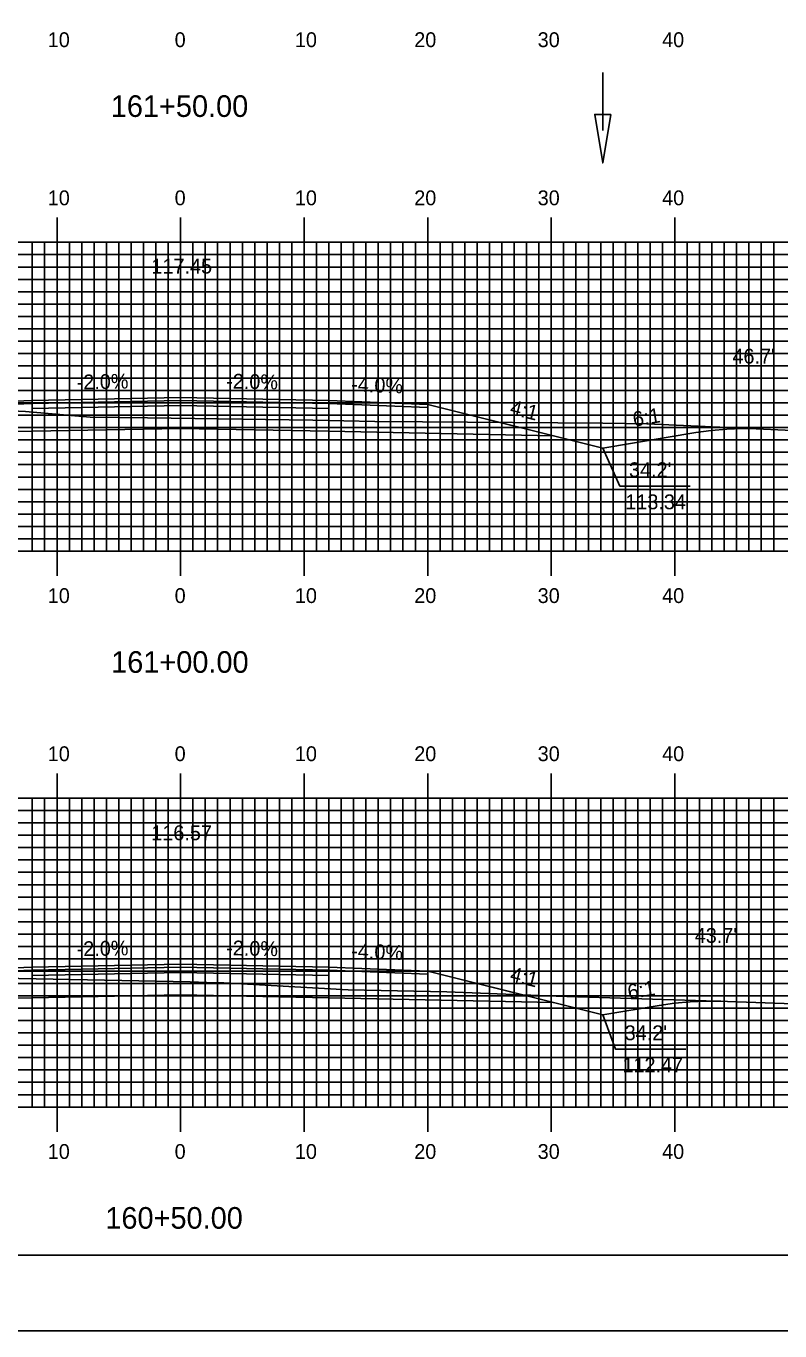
# Model space of a CAD drawing. Extents: x 1780286 to 1780629, y 442591 to 442811.
# Drawn here: x 1780439.4 to 1780500.4, y 442590.5 to 442696.2 of the extents above; entities that cross this region are included whole.
import ezdxf

# ---------------------------------------------------------------- set-up
doc = ezdxf.new("R2010")
doc.units = 0
for name, color, linetype in [('ANNOTATION', 7, 'Continuous'), ('BORDER', 7, 'Continuous'), ('D_Drainage_Ditch_Line', 7, 'Continuous'), ('D_Roadway_Centerline', 7, 'Continuous'), ('D_Roadway_Centerline_Text', 7, 'Continuous'), ('D_Roadway_Edge_Shoulder', 7, 'Continuous'), ('D_Roadway_Edge_TW', 7, 'Continuous'), ('D_Roadway_Pavement', 7, 'Continuous'), ('D_Roadway_SlopeLines', 7, 'Continuous'), ('D_Roadway_SubGrade', 7, 'Continuous'), ('D_Text_Standard', 7, 'Continuous'), ('H_V ANNOTATION', 7, 'Continuous'), ('MAJOR', 7, 'Continuous'), ('MINOR', 7, 'Continuous'), ('PLOT BOUNDARY', 7, 'Continuous'), ('S_Roadway_Centerline', 7, 'Continuous')]:
    doc.layers.add(name, color=color, linetype=linetype)

msp = doc.modelspace()

# ---------------------------------------------------------------- linework, layer by layer
at = {"layer": 'ANNOTATION'}
for points in [[(1780493.11, 442658.93), (1780487.42, 442658.93), (1780486.04, 442662.01)], [(1780492.76, 442613.35), (1780487.07, 442613.35), (1780486.04, 442616.13)]]:
    msp.add_lwpolyline(points, dxfattribs=at)
at = {"layer": 'BORDER'}
msp.add_lwpolyline([(1780302.27, 442596.67), (1780622.27, 442596.67), (1780622.27, 442806.67), (1780302.27, 442806.67)], close=True, dxfattribs=at)
at = {"layer": 'D_Drainage_Ditch_Line'}
msp.add_line((1780486.04, 442687.71), (1780486.04, 442692.41), dxfattribs=at)
msp.add_lwpolyline([(1780486.7, 442689.02), (1780485.39, 442689.02), (1780486.04, 442685.09)], close=True, dxfattribs=at)
at = {"layer": 'D_Roadway_Centerline'}
for points in [[(1780390.14, 442666.22), (1780391.39, 442666.18), (1780392.64, 442666.09), (1780393.89, 442665.95), (1780395.14, 442665.77), (1780417.69, 442662.01), (1780421.69, 442663.01), (1780431.87, 442665.55), (1780439.87, 442665.87), (1780451.87, 442666.11), (1780463.87, 442665.87), (1780471.87, 442665.55), (1780482.04, 442663.01), (1780486.04, 442662.01), (1780493.57, 442663.26), (1780494.82, 442663.44), (1780496.07, 442663.55), (1780497.32, 442663.59), (1780498.57, 442663.57)], [(1780395.38, 442619.56), (1780396.63, 442619.48), (1780397.88, 442619.36), (1780399.13, 442619.21), (1780400.38, 442619.02), (1780417.69, 442616.13), (1780421.69, 442617.13), (1780431.87, 442619.68), (1780439.87, 442620), (1780451.87, 442620.24), (1780463.87, 442620), (1780471.87, 442619.68), (1780482.04, 442617.13), (1780486.04, 442616.13), (1780490.6, 442616.89), (1780491.85, 442617.07), (1780493.1, 442617.19), (1780494.35, 442617.24), (1780495.6, 442617.23)]]:
    msp.add_lwpolyline(points, dxfattribs=at)
at = {"layer": 'D_Roadway_Edge_Shoulder'}
for points in [[(1780439.87, 442665.87), (1780431.87, 442665.55), (1780431.87, 442665.3), (1780439.87, 442665.62)], [(1780463.87, 442665.87), (1780471.87, 442665.55), (1780471.87, 442665.3), (1780463.87, 442665.62)], [(1780439.87, 442620), (1780431.87, 442619.68), (1780431.87, 442619.43), (1780439.87, 442619.75)], [(1780463.87, 442620), (1780471.87, 442619.68), (1780471.87, 442619.43), (1780463.87, 442619.75)]]:
    msp.add_lwpolyline(points, close=True, dxfattribs=at)
at = {"layer": 'D_Roadway_Edge_TW'}
for points in [[(1780439.87, 442665.62), (1780439.87, 442665.87), (1780451.87, 442666.11), (1780463.87, 442665.87), (1780463.87, 442665.62), (1780451.87, 442665.86)], [(1780439.87, 442619.75), (1780439.87, 442620), (1780451.87, 442620.24), (1780463.87, 442620), (1780463.87, 442619.75), (1780451.87, 442619.99)]]:
    msp.add_lwpolyline(points, close=True, dxfattribs=at)
at = {"layer": 'D_Roadway_Pavement'}
for points in [[(1780439.87, 442665.21), (1780439.87, 442665.62), (1780451.87, 442665.86), (1780463.87, 442665.62), (1780463.87, 442665.21), (1780451.87, 442665.45)], [(1780439.87, 442619.33), (1780439.87, 442619.75), (1780451.87, 442619.99), (1780463.87, 442619.75), (1780463.87, 442619.33), (1780451.87, 442619.57)]]:
    msp.add_lwpolyline(points, close=True, dxfattribs=at)
at = {"layer": 'D_Roadway_SlopeLines'}
for points in [[(1780471.87, 442665.55), (1780486.04, 442662.01)], [(1780486.04, 442662.01), (1780493.57, 442663.26), (1780494.82, 442663.44), (1780496.07, 442663.55), (1780497.32, 442663.59), (1780498.57, 442663.57)], [(1780471.87, 442619.68), (1780486.04, 442616.13)], [(1780486.04, 442616.13), (1780490.6, 442616.89), (1780491.85, 442617.07), (1780493.1, 442617.19), (1780494.35, 442617.24), (1780495.6, 442617.23)]]:
    msp.add_lwpolyline(points, dxfattribs=at)
at = {"layer": 'D_Roadway_SubGrade'}
for points in [[(1780439.87, 442663.37), (1780421.69, 442663.01), (1780431.87, 442665.55), (1780431.87, 442665.3), (1780439.87, 442665.62), (1780451.87, 442665.86), (1780463.87, 442665.62), (1780471.87, 442665.3), (1780471.87, 442665.55), (1780482.04, 442663.01), (1780463.87, 442663.37), (1780451.87, 442663.61)], [(1780439.87, 442617.5), (1780421.69, 442617.13), (1780431.87, 442619.68), (1780431.87, 442619.43), (1780439.87, 442619.75), (1780451.87, 442619.99), (1780463.87, 442619.75), (1780471.87, 442619.43), (1780471.87, 442619.68), (1780482.04, 442617.13), (1780463.87, 442617.5), (1780451.87, 442617.74)]]:
    msp.add_lwpolyline(points, close=True, dxfattribs=at)
at = {"layer": 'MAJOR'}
for p, q in [((1780441.87, 442680.67), (1780441.87, 442678.67)), ((1780451.87, 442680.67), (1780451.87, 442678.67)), ((1780461.87, 442680.67), (1780461.87, 442678.67)), ((1780471.87, 442680.67), (1780471.87, 442678.67)), ((1780481.87, 442680.67), (1780481.87, 442678.67)), ((1780491.87, 442680.67), (1780491.87, 442678.67)), ((1780311.87, 442678.67), (1780591.87, 442678.67)), ((1780311.87, 442678.67), (1780591.87, 442678.67)), ((1780441.87, 442653.67), (1780441.87, 442678.67)), ((1780451.87, 442653.67), (1780451.87, 442678.67)), ((1780461.87, 442653.67), (1780461.87, 442678.67)), ((1780471.87, 442653.67), (1780471.87, 442678.67)), ((1780481.87, 442653.67), (1780481.87, 442678.67)), ((1780491.87, 442653.67), (1780491.87, 442678.67)), ((1780311.87, 442673.67), (1780591.87, 442673.67)), ((1780311.87, 442668.67), (1780591.87, 442668.67)), ((1780311.87, 442663.67), (1780591.87, 442663.67)), ((1780311.87, 442658.67), (1780591.87, 442658.67)), ((1780311.87, 442653.67), (1780591.87, 442653.67)), ((1780311.87, 442653.67), (1780591.87, 442653.67)), ((1780441.87, 442651.66), (1780441.87, 442653.67)), ((1780451.87, 442651.66), (1780451.87, 442653.67)), ((1780461.87, 442651.66), (1780461.87, 442653.67)), ((1780471.87, 442651.66), (1780471.87, 442653.67)), ((1780481.87, 442651.66), (1780481.87, 442653.67)), ((1780491.87, 442651.66), (1780491.87, 442653.67)), ((1780441.87, 442635.67), (1780441.87, 442633.67)), ((1780451.87, 442635.67), (1780451.87, 442633.67)), ((1780461.87, 442635.67), (1780461.87, 442633.67)), ((1780471.87, 442635.67), (1780471.87, 442633.67)), ((1780481.87, 442635.67), (1780481.87, 442633.67)), ((1780491.87, 442635.67), (1780491.87, 442633.67)), ((1780311.87, 442633.67), (1780591.87, 442633.67)), ((1780311.87, 442633.67), (1780591.87, 442633.67)), ((1780441.87, 442608.67), (1780441.87, 442633.67)), ((1780451.87, 442608.67), (1780451.87, 442633.67)), ((1780461.87, 442608.67), (1780461.87, 442633.67)), ((1780471.87, 442608.67), (1780471.87, 442633.67)), ((1780481.87, 442608.67), (1780481.87, 442633.67)), ((1780491.87, 442608.67), (1780491.87, 442633.67)), ((1780311.87, 442628.67), (1780591.87, 442628.67)), ((1780311.87, 442623.67), (1780591.87, 442623.67)), ((1780311.87, 442618.67), (1780591.87, 442618.67)), ((1780311.87, 442613.67), (1780591.87, 442613.67)), ((1780311.87, 442608.67), (1780591.87, 442608.67)), ((1780311.87, 442608.67), (1780591.87, 442608.67)), ((1780441.87, 442606.66), (1780441.87, 442608.67)), ((1780451.87, 442606.66), (1780451.87, 442608.67)), ((1780461.87, 442606.66), (1780461.87, 442608.67)), ((1780471.87, 442606.66), (1780471.87, 442608.67)), ((1780481.87, 442606.66), (1780481.87, 442608.67)), ((1780491.87, 442606.66), (1780491.87, 442608.67))]:
    msp.add_line(p, q, dxfattribs=at)
at = {"layer": 'MINOR'}
for p, q in [((1780439.87, 442653.67), (1780439.87, 442678.67)), ((1780440.87, 442653.67), (1780440.87, 442678.67)), ((1780442.87, 442653.67), (1780442.87, 442678.67)), ((1780443.87, 442653.67), (1780443.87, 442678.67)), ((1780444.87, 442653.67), (1780444.87, 442678.67)), ((1780445.87, 442653.67), (1780445.87, 442678.67)), ((1780446.87, 442653.67), (1780446.87, 442678.67)), ((1780447.87, 442653.67), (1780447.87, 442678.67)), ((1780448.87, 442653.67), (1780448.87, 442678.67)), ((1780449.87, 442653.67), (1780449.87, 442678.67)), ((1780450.87, 442653.67), (1780450.87, 442678.67)), ((1780452.87, 442653.67), (1780452.87, 442678.67)), ((1780453.87, 442653.67), (1780453.87, 442678.67)), ((1780454.87, 442653.67), (1780454.87, 442678.67)), ((1780455.87, 442653.67), (1780455.87, 442678.67)), ((1780456.87, 442653.67), (1780456.87, 442678.67)), ((1780457.87, 442653.67), (1780457.87, 442678.67)), ((1780458.87, 442653.67), (1780458.87, 442678.67)), ((1780459.87, 442653.67), (1780459.87, 442678.67)), ((1780460.87, 442653.67), (1780460.87, 442678.67)), ((1780462.87, 442653.67), (1780462.87, 442678.67)), ((1780463.87, 442653.67), (1780463.87, 442678.67)), ((1780464.87, 442653.67), (1780464.87, 442678.67)), ((1780465.87, 442653.67), (1780465.87, 442678.67)), ((1780466.87, 442653.67), (1780466.87, 442678.67)), ((1780467.87, 442653.67), (1780467.87, 442678.67)), ((1780468.87, 442653.67), (1780468.87, 442678.67)), ((1780469.87, 442653.67), (1780469.87, 442678.67)), ((1780470.87, 442653.67), (1780470.87, 442678.67)), ((1780472.87, 442653.67), (1780472.87, 442678.67)), ((1780473.87, 442653.67), (1780473.87, 442678.67)), ((1780474.87, 442653.67), (1780474.87, 442678.67)), ((1780475.87, 442653.67), (1780475.87, 442678.67)), ((1780476.87, 442653.67), (1780476.87, 442678.67)), ((1780477.87, 442653.67), (1780477.87, 442678.67)), ((1780478.87, 442653.67), (1780478.87, 442678.67)), ((1780479.87, 442653.67), (1780479.87, 442678.67)), ((1780480.87, 442653.67), (1780480.87, 442678.67)), ((1780482.87, 442653.67), (1780482.87, 442678.67)), ((1780483.87, 442653.67), (1780483.87, 442678.67)), ((1780484.87, 442653.67), (1780484.87, 442678.67)), ((1780485.87, 442653.67), (1780485.87, 442678.67)), ((1780486.87, 442653.67), (1780486.87, 442678.67)), ((1780487.87, 442653.67), (1780487.87, 442678.67)), ((1780488.87, 442653.67), (1780488.87, 442678.67)), ((1780489.87, 442653.67), (1780489.87, 442678.67)), ((1780490.87, 442653.67), (1780490.87, 442678.67)), ((1780492.87, 442653.67), (1780492.87, 442678.67)), ((1780493.87, 442653.67), (1780493.87, 442678.67)), ((1780494.87, 442653.67), (1780494.87, 442678.67)), ((1780495.87, 442653.67), (1780495.87, 442678.67)), ((1780496.87, 442653.67), (1780496.87, 442678.67)), ((1780497.87, 442653.67), (1780497.87, 442678.67)), ((1780498.87, 442653.67), (1780498.87, 442678.67)), ((1780499.87, 442653.67), (1780499.87, 442678.67)), ((1780311.87, 442677.67), (1780591.87, 442677.67)), ((1780311.87, 442676.67), (1780591.87, 442676.67)), ((1780311.87, 442675.67), (1780591.87, 442675.67)), ((1780311.87, 442674.67), (1780591.87, 442674.67)), ((1780311.87, 442672.67), (1780591.87, 442672.67)), ((1780311.87, 442671.67), (1780591.87, 442671.67)), ((1780311.87, 442670.67), (1780591.87, 442670.67)), ((1780311.87, 442669.67), (1780591.87, 442669.67)), ((1780311.87, 442667.67), (1780591.87, 442667.67)), ((1780311.87, 442666.67), (1780591.87, 442666.67)), ((1780311.87, 442665.67), (1780591.87, 442665.67)), ((1780311.87, 442664.67), (1780591.87, 442664.67)), ((1780311.87, 442662.67), (1780591.87, 442662.67)), ((1780311.87, 442661.67), (1780591.87, 442661.67)), ((1780311.87, 442660.67), (1780591.87, 442660.67)), ((1780311.87, 442659.67), (1780591.87, 442659.67)), ((1780311.87, 442657.67), (1780591.87, 442657.67)), ((1780311.87, 442656.67), (1780591.87, 442656.67)), ((1780311.87, 442655.67), (1780591.87, 442655.67)), ((1780311.87, 442654.67), (1780591.87, 442654.67)), ((1780439.87, 442608.67), (1780439.87, 442633.67)), ((1780440.87, 442608.67), (1780440.87, 442633.67)), ((1780442.87, 442608.67), (1780442.87, 442633.67)), ((1780443.87, 442608.67), (1780443.87, 442633.67)), ((1780444.87, 442608.67), (1780444.87, 442633.67)), ((1780445.87, 442608.67), (1780445.87, 442633.67)), ((1780446.87, 442608.67), (1780446.87, 442633.67)), ((1780447.87, 442608.67), (1780447.87, 442633.67)), ((1780448.87, 442608.67), (1780448.87, 442633.67)), ((1780449.87, 442608.67), (1780449.87, 442633.67)), ((1780450.87, 442608.67), (1780450.87, 442633.67)), ((1780452.87, 442608.67), (1780452.87, 442633.67)), ((1780453.87, 442608.67), (1780453.87, 442633.67)), ((1780454.87, 442608.67), (1780454.87, 442633.67)), ((1780455.87, 442608.67), (1780455.87, 442633.67)), ((1780456.87, 442608.67), (1780456.87, 442633.67)), ((1780457.87, 442608.67), (1780457.87, 442633.67)), ((1780458.87, 442608.67), (1780458.87, 442633.67)), ((1780459.87, 442608.67), (1780459.87, 442633.67)), ((1780460.87, 442608.67), (1780460.87, 442633.67)), ((1780462.87, 442608.67), (1780462.87, 442633.67)), ((1780463.87, 442608.67), (1780463.87, 442633.67)), ((1780464.87, 442608.67), (1780464.87, 442633.67)), ((1780465.87, 442608.67), (1780465.87, 442633.67)), ((1780466.87, 442608.67), (1780466.87, 442633.67)), ((1780467.87, 442608.67), (1780467.87, 442633.67)), ((1780468.87, 442608.67), (1780468.87, 442633.67)), ((1780469.87, 442608.67), (1780469.87, 442633.67)), ((1780470.87, 442608.67), (1780470.87, 442633.67)), ((1780472.87, 442608.67), (1780472.87, 442633.67)), ((1780473.87, 442608.67), (1780473.87, 442633.67)), ((1780474.87, 442608.67), (1780474.87, 442633.67)), ((1780475.87, 442608.67), (1780475.87, 442633.67)), ((1780476.87, 442608.67), (1780476.87, 442633.67)), ((1780477.87, 442608.67), (1780477.87, 442633.67)), ((1780478.87, 442608.67), (1780478.87, 442633.67)), ((1780479.87, 442608.67), (1780479.87, 442633.67)), ((1780480.87, 442608.67), (1780480.87, 442633.67)), ((1780482.87, 442608.67), (1780482.87, 442633.67)), ((1780483.87, 442608.67), (1780483.87, 442633.67)), ((1780484.87, 442608.67), (1780484.87, 442633.67)), ((1780485.87, 442608.67), (1780485.87, 442633.67)), ((1780486.87, 442608.67), (1780486.87, 442633.67)), ((1780487.87, 442608.67), (1780487.87, 442633.67)), ((1780488.87, 442608.67), (1780488.87, 442633.67)), ((1780489.87, 442608.67), (1780489.87, 442633.67)), ((1780490.87, 442608.67), (1780490.87, 442633.67)), ((1780492.87, 442608.67), (1780492.87, 442633.67)), ((1780493.87, 442608.67), (1780493.87, 442633.67)), ((1780494.87, 442608.67), (1780494.87, 442633.67)), ((1780495.87, 442608.67), (1780495.87, 442633.67)), ((1780496.87, 442608.67), (1780496.87, 442633.67)), ((1780497.87, 442608.67), (1780497.87, 442633.67)), ((1780498.87, 442608.67), (1780498.87, 442633.67)), ((1780499.87, 442608.67), (1780499.87, 442633.67)), ((1780311.87, 442632.67), (1780591.87, 442632.67)), ((1780311.87, 442631.67), (1780591.87, 442631.67)), ((1780311.87, 442630.67), (1780591.87, 442630.67)), ((1780311.87, 442629.67), (1780591.87, 442629.67)), ((1780311.87, 442627.67), (1780591.87, 442627.67)), ((1780311.87, 442626.67), (1780591.87, 442626.67)), ((1780311.87, 442625.67), (1780591.87, 442625.67)), ((1780311.87, 442624.67), (1780591.87, 442624.67)), ((1780311.87, 442622.67), (1780591.87, 442622.67)), ((1780311.87, 442621.67), (1780591.87, 442621.67)), ((1780311.87, 442620.67), (1780591.87, 442620.67)), ((1780311.87, 442619.67), (1780591.87, 442619.67)), ((1780311.87, 442617.67), (1780591.87, 442617.67)), ((1780311.87, 442616.67), (1780591.87, 442616.67)), ((1780311.87, 442615.67), (1780591.87, 442615.67)), ((1780311.87, 442614.67), (1780591.87, 442614.67)), ((1780311.87, 442612.67), (1780591.87, 442612.67)), ((1780311.87, 442611.67), (1780591.87, 442611.67)), ((1780311.87, 442610.67), (1780591.87, 442610.67)), ((1780311.87, 442609.67), (1780591.87, 442609.67))]:
    msp.add_line(p, q, dxfattribs=at)
at = {"layer": 'PLOT BOUNDARY'}
msp.add_lwpolyline([(1780286.08, 442590.55), (1780626.08, 442590.55), (1780626.08, 442810.55), (1780286.08, 442810.55)], close=True, dxfattribs=at)
at = {"layer": 'S_Roadway_Centerline'}
for points in [[(1780311.87, 442669.26), (1780313.82, 442669.05), (1780317.25, 442668.73), (1780327.63, 442667.81), (1780336.57, 442667.6), (1780344.45, 442667.39), (1780357.65, 442666.97), (1780362.28, 442666.8), (1780381.18, 442666.41), (1780385.56, 442666.15), (1780390.26, 442666.22), (1780405.31, 442666), (1780413.62, 442665.77), (1780426.7, 442665.56), (1780439.31, 442664.98), (1780444.55, 442664.51), (1780449.19, 442664.46), (1780462.56, 442664.28), (1780467.58, 442664.17), (1780471.44, 442664.14), (1780486.05, 442664.03), (1780489.63, 442663.98), (1780509.62, 442663.05)], [(1780386.91, 442619.48), (1780395.43, 442619.57), (1780405.3, 442619.05), (1780407.69, 442618.94), (1780409.95, 442619.02), (1780428.41, 442619.28), (1780433.22, 442619.18), (1780452.65, 442618.8), (1780453.99, 442618.75), (1780455.37, 442618.72), (1780465.44, 442618.15), (1780473.41, 442618), (1780482.26, 442617.65), (1780496.12, 442617.22), (1780505.3, 442616.88)]]:
    msp.add_lwpolyline(points, dxfattribs=at)

# ---------------------------------------------------------------- texts
at = {"layer": 'ANNOTATION'}
for s, rotation, p in [('-2.0%', 1.1458, (1780443.47, 442666.75)), ('-2.0%', 358.8542, (1780455.55, 442666.84)), ('-4.0%', 357.7094, (1780465.66, 442666.6)), ('4:1', 345.9638, (1780478.46, 442664.77)), ('6:1', 9.4625, (1780488.57, 442663.74)), ('-2.0%', 1.1458, (1780443.47, 442620.87)), ('-2.0%', 358.8542, (1780455.55, 442620.96)), ('-4.0%', 357.7094, (1780465.66, 442620.73)), ('4:1', 345.9638, (1780478.46, 442618.89)), ('6:1', 9.4625, (1780488.15, 442617.38))]:
    msp.add_text(s, height=1.2, rotation=rotation, dxfattribs=at).set_placement(p)
for s, p in [("34.2'", (1780488.16, 442659.66)), ('113.34', (1780487.86, 442657.06)), ("34.2'", (1780487.81, 442614.08)), ('112.47', (1780487.63, 442611.48))]:
    msp.add_text(s, height=1.2, dxfattribs=at).set_placement(p)
at = {"layer": 'D_Roadway_Centerline'}
for s, p in [('C', (1780451.86, 442666.11)), ('L', (1780451.87, 442666.11)), ('C', (1780451.86, 442620.24)), ('L', (1780451.87, 442620.23))]:
    msp.add_text(s, height=0.0146, dxfattribs=at).set_placement(p)
at = {"layer": 'D_Roadway_Centerline_Text'}
for s, p in [('117.45', (1780449.51, 442676.14)), ('116.57', (1780449.5, 442630.27))]:
    msp.add_text(s, height=1.2, dxfattribs=at).set_placement(p)
at = {"layer": 'D_Text_Standard'}
for s, p in [("46.7'", (1780496.53, 442668.85)), ("43.7'", (1780493.48, 442621.96))]:
    msp.add_text(s, height=1.2, dxfattribs=at).set_placement(p)
at = {"layer": 'H_V ANNOTATION'}
for s, height, p in [('10', 1.2, (1780441.12, 442694.47)), ('0', 1.2, (1780451.39, 442694.47)), ('10', 1.2, (1780461.12, 442694.47)), ('20', 1.2, (1780470.78, 442694.47)), ('30', 1.2, (1780480.77, 442694.47)), ('40', 1.2, (1780490.84, 442694.47)), ('161+50.00', 1.75, (1780446.22, 442688.82)), ('10', 1.2, (1780441.12, 442681.67)), ('0', 1.2, (1780451.39, 442681.67)), ('10', 1.2, (1780461.12, 442681.67)), ('20', 1.2, (1780470.78, 442681.67)), ('30', 1.2, (1780480.77, 442681.67)), ('40', 1.2, (1780490.84, 442681.67)), ('10', 1.2, (1780441.12, 442649.47)), ('0', 1.2, (1780451.39, 442649.47)), ('10', 1.2, (1780461.12, 442649.47)), ('20', 1.2, (1780470.78, 442649.47)), ('30', 1.2, (1780480.77, 442649.47)), ('40', 1.2, (1780490.84, 442649.47)), ('161+00.00', 1.75, (1780446.25, 442643.82)), ('10', 1.2, (1780441.12, 442636.67)), ('0', 1.2, (1780451.39, 442636.67)), ('10', 1.2, (1780461.12, 442636.67)), ('20', 1.2, (1780470.78, 442636.67)), ('30', 1.2, (1780480.77, 442636.67)), ('40', 1.2, (1780490.84, 442636.67)), ('10', 1.2, (1780441.12, 442604.47)), ('0', 1.2, (1780451.39, 442604.47)), ('10', 1.2, (1780461.12, 442604.47)), ('20', 1.2, (1780470.78, 442604.47)), ('30', 1.2, (1780480.77, 442604.47)), ('40', 1.2, (1780490.84, 442604.47)), ('160+50.00', 1.75, (1780445.78, 442598.82))]:
    msp.add_text(s, height=height, dxfattribs=at).set_placement(p)

doc.saveas('drawing.dxf')
